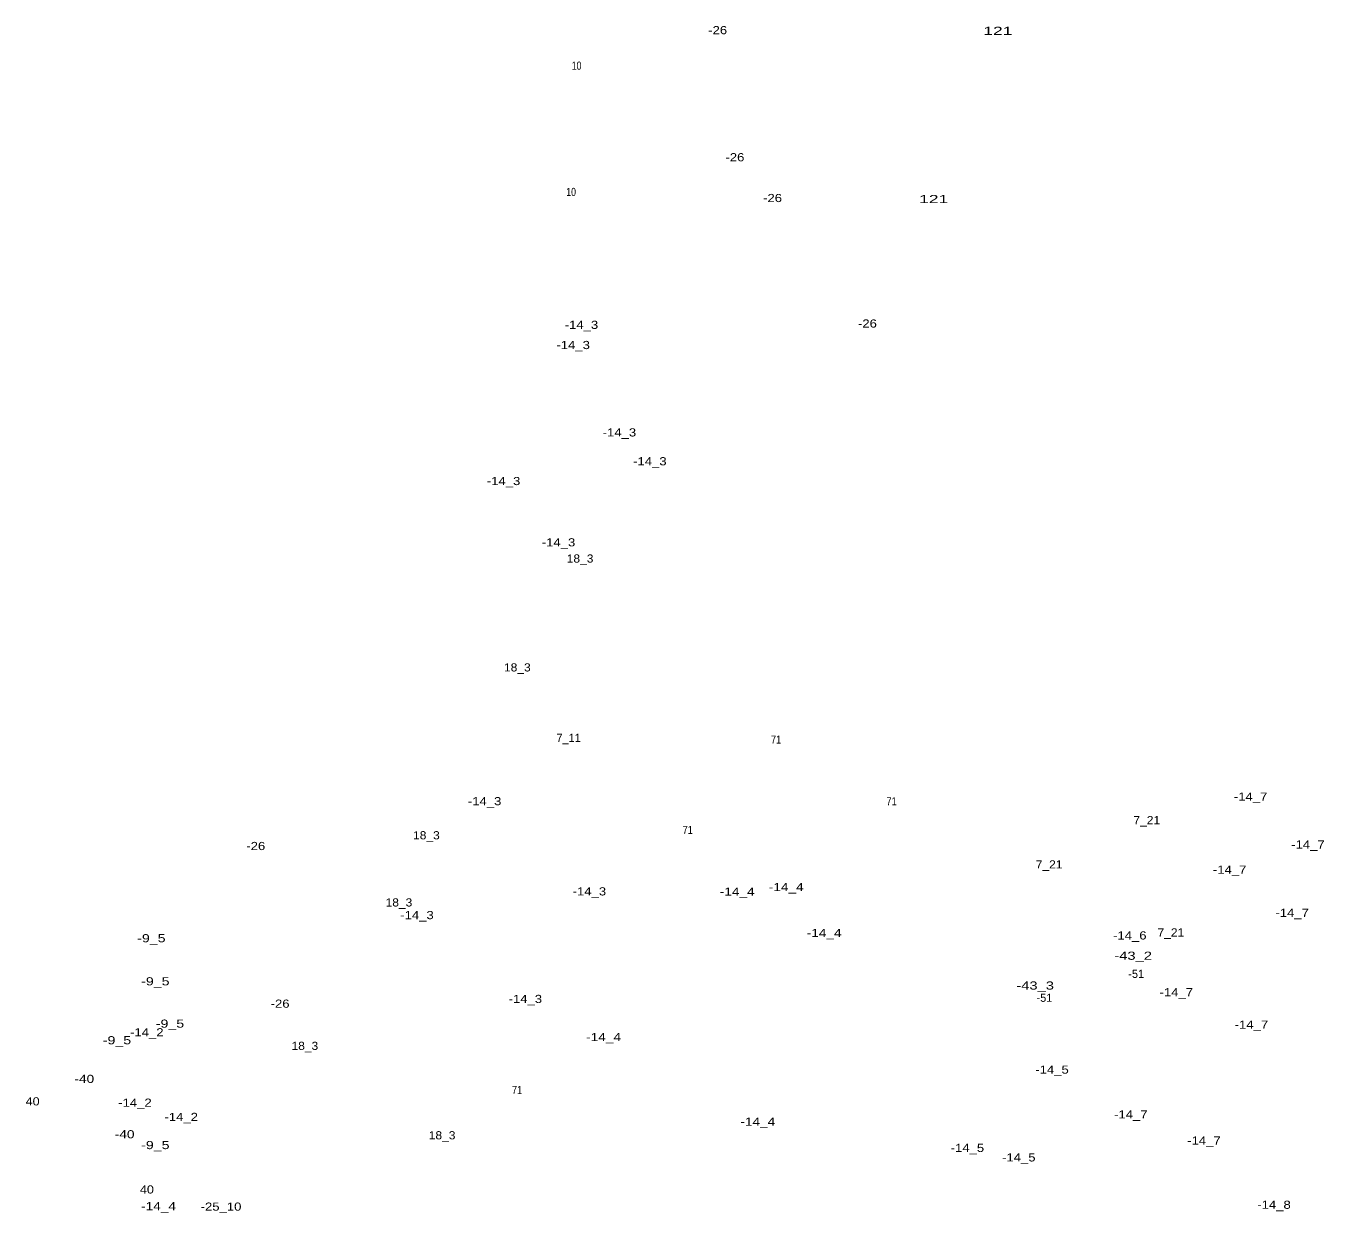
# Model space of a CAD drawing. Extents: x -663705 to -661666, y -1002081 to -999269.
# Drawn here: x -662403 to -661767, y -1001175 to -1000593 of the extents above; entities that cross this region are included whole.
import ezdxf
from ezdxf.enums import TextEntityAlignment as Align

# ---------------------------------------------------------------- set-up
doc = ezdxf.new("R2010")
doc.units = 0
doc.header["$LTSCALE"] = 1.6
doc.layers.add('24', color=7, linetype='Continuous')

msp = doc.modelspace()

# ---------------------------------------------------------------- texts
at = {"layer": '24'}
for s, width, p in [('-26', 1.2, (-662064.23, -1000597.37)), ('121', 1.6, (-661926.864, -1000597.7)), ('10', 0.8, (-662133.4, -1000614.78)), ('-26', 1.2, (-662055.77, -1000659.68)), ('10', 0.8, (-662136.09, -1000676.7)), ('-26', 1.2, (-662037.32, -1000679.68)), ('121', 1.6, (-661958.314, -1000680.19)), ('-14_3', 1.2, (-662131.01, -1000741.87)), ('-26', 1.2, (-661990.8, -1000741.22)), ('-14_3', 1.2, (-662135.079, -1000751.76)), ('-14_3', 1.2, (-662112.4, -1000794.62)), ('-14_3', 1.2, (-662097.47, -1000808.76)), ('-14_3', 1.2, (-662169.199, -1000818.46)), ('-14_3', 1.2, (-662142.26, -1000848.52)), ('18_3', 1.1, (-662131.69, -1000856.46)), ('18_3', 1.1, (-662162.45, -1000909.86)), ('71', 0.85, (-662035.581, -1000945.27)), ('-14_3', 1.2, (-662178.51, -1000975.46)), ('71', 0.85, (-661978.971, -1000975.52)), ('-14_7', 1.2, (-661802.91, -1000973.22)), ('7_21', 1.1, (-661853.84, -1000984.74)), ('18_3', 1.1, (-662207.04, -1000992.17)), ('71', 0.85, (-662078.88, -1000989.57)), ('-26', 1.2, (-662290.7, -1000997.44)), ('-14_7', 1.2, (-661774.8, -1000996.69)), ('7_21', 1.1, (-661901.72, -1001006.46)), ('-14_7', 1.2, (-661813.2, -1001009.04)), ('-14_3', 1.2, (-662127.13, -1001019.68)), ('-14_4', 1.25, (-662054.64, -1001019.81)), ('-14_4', 1.25, (-662030.64, -1001017.58)), ('18_3', 1.1, (-662220.5, -1001025.11)), ('-14_3', 1.2, (-662211.66, -1001031.32)), ('-14_7', 1.2, (-661782.56, -1001030.18)), ('-9_5', 1.3, (-662341.9, -1001042.65)), ('-14_4', 1.25, (-662012.03, -1001040.08)), ('-14_6', 1.2, (-661862.14, -1001041.29)), ('7_21', 1.1, (-661842.01, -1001039.82)), ('-43_2', 1.35, (-661860.53, -1001051.24)), ('-9_5', 1.3, (-662339.96, -1001063.79)), ('-43_3', 1.35, (-661908.58, -1001065.86)), ('-14_7', 1.2, (-661839.36, -1001069.15)), ('-26', 1.2, (-662278.78, -1001074.75)), ('-14_3', 1.2, (-662158.54, -1001072.43)), ('-14_2', 1.2, (-662344.13, -1001088.79)), ('-9_5', 1.3, (-662332.78, -1001084.54)), ('-14_7', 1.2, (-661802.52, -1001085.05)), ('-9_5', 1.3, (-662358.76, -1001092.68)), ('18_3', 1.1, (-662266.64, -1001095.44)), ('-14_4', 1.25, (-662120.17, -1001091.12)), ('-14_5', 1.2, (-661900.29, -1001107.08)), ('-40', 1.25, (-662374.77, -1001111.63)), ('71', 0.85, (-662162.571, -1001117.08)), ('40', 1.15, (-662400.11, -1001122.65)), ('-14_2', 1.2, (-662349.949, -1001123.3)), ('-14_2', 1.2, (-662327.26, -1001130.29)), ('-14_4', 1.25, (-662044.56, -1001132.62)), ('-14_7', 1.2, (-661861.65, -1001129.06)), ('-40', 1.25, (-662355, -1001138.78)), ('18_3', 1.1, (-662199.35, -1001139.29)), ('-9_5', 1.3, (-662339.96, -1001144.08)), ('-14_5', 1.2, (-661941.78, -1001145.48)), ('-14_7', 1.2, (-661825.79, -1001141.86)), ('-14_5', 1.2, (-661916.569, -1001150.13)), ('40', 1.15, (-662344.09, -1001165.86)), ('-14_8', 1.2, (-661791.449, -1001173.36)), ('-14_4', 1.25, (-662338.39, -1001174.06)), ('-25_10', 1.2, (-662307.75, -1001174.27))]:
    msp.add_text(s, height=4, dxfattribs=dict(at, width=width)).set_placement(p, align=Align.CENTER)
for s, p in [('7_11', (-662137.32, -1000944.38)), ('-51', (-661859.02, -1001060.12)), ('-51', (-661904, -1001071.85))]:
    msp.add_text(s, height=4, dxfattribs=at).set_placement(p, align=Align.CENTER)

doc.saveas('drawing.dxf')
